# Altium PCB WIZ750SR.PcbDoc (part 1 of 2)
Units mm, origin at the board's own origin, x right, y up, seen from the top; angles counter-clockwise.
Board outline 45 x 30 mm, 4 copper layers (Top Layer, Internal Plane 1, Internal Plane 2, Bottom Layer); 93 components, 69 nets, 325 pads, 127 vias.
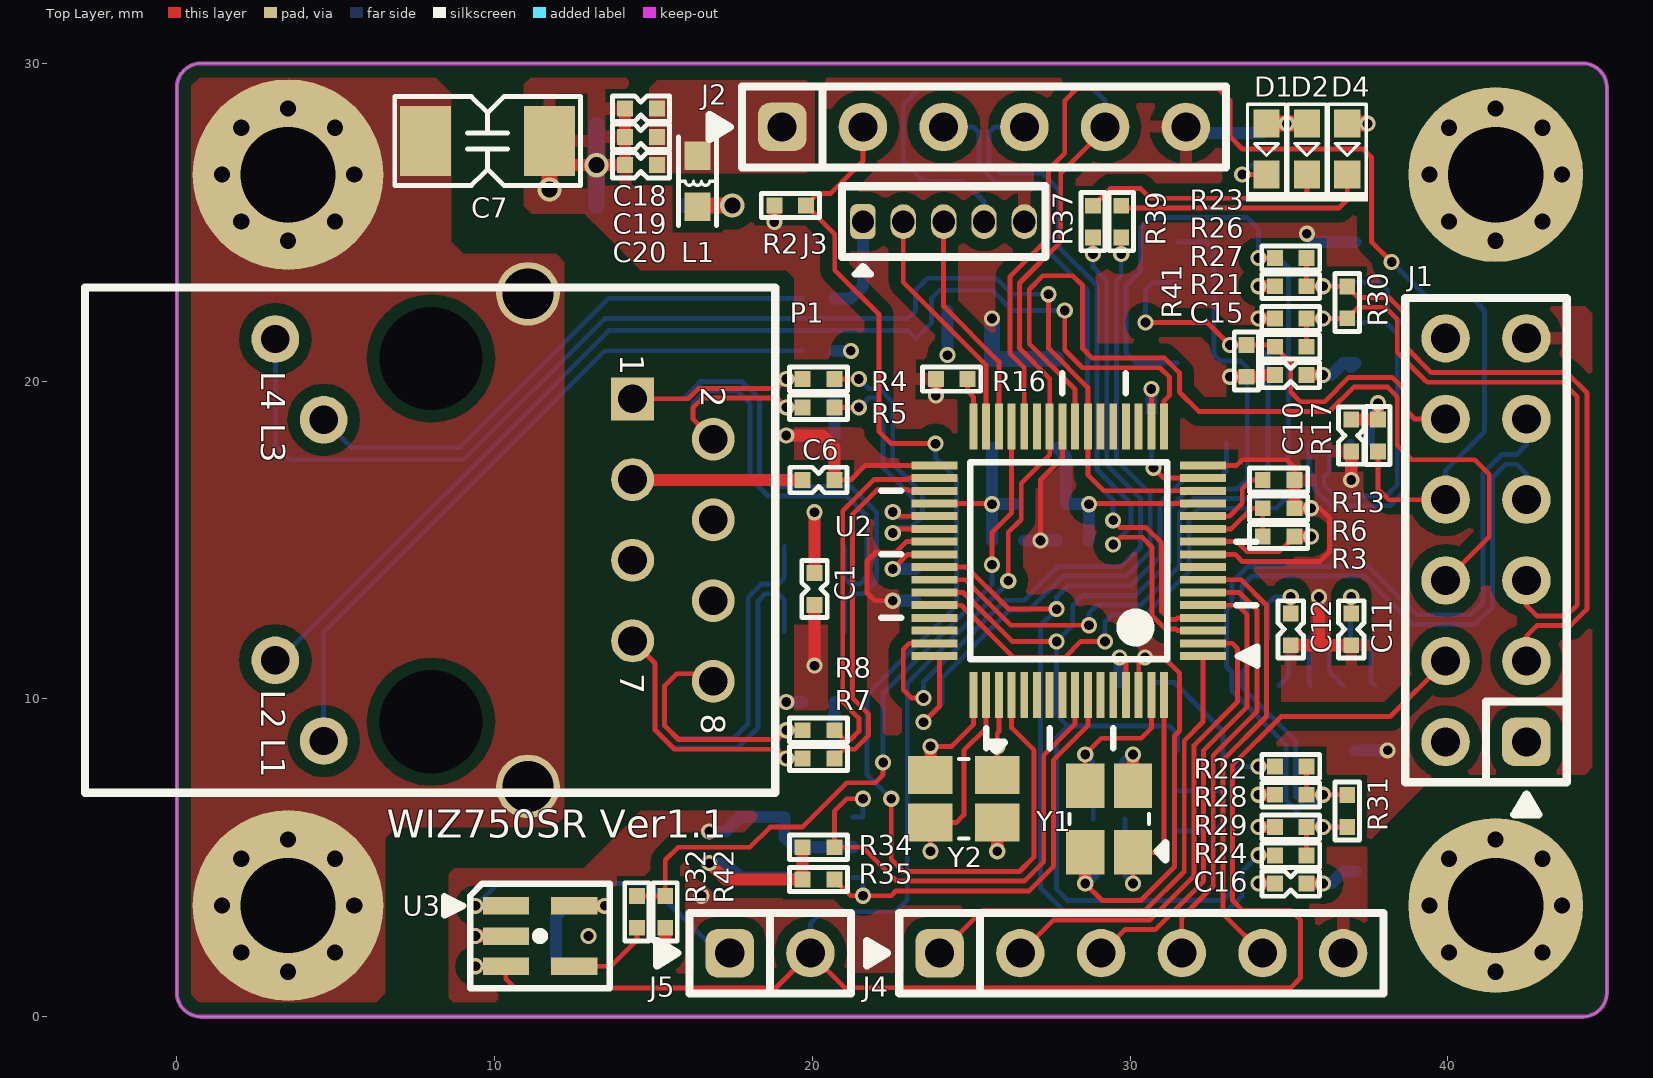
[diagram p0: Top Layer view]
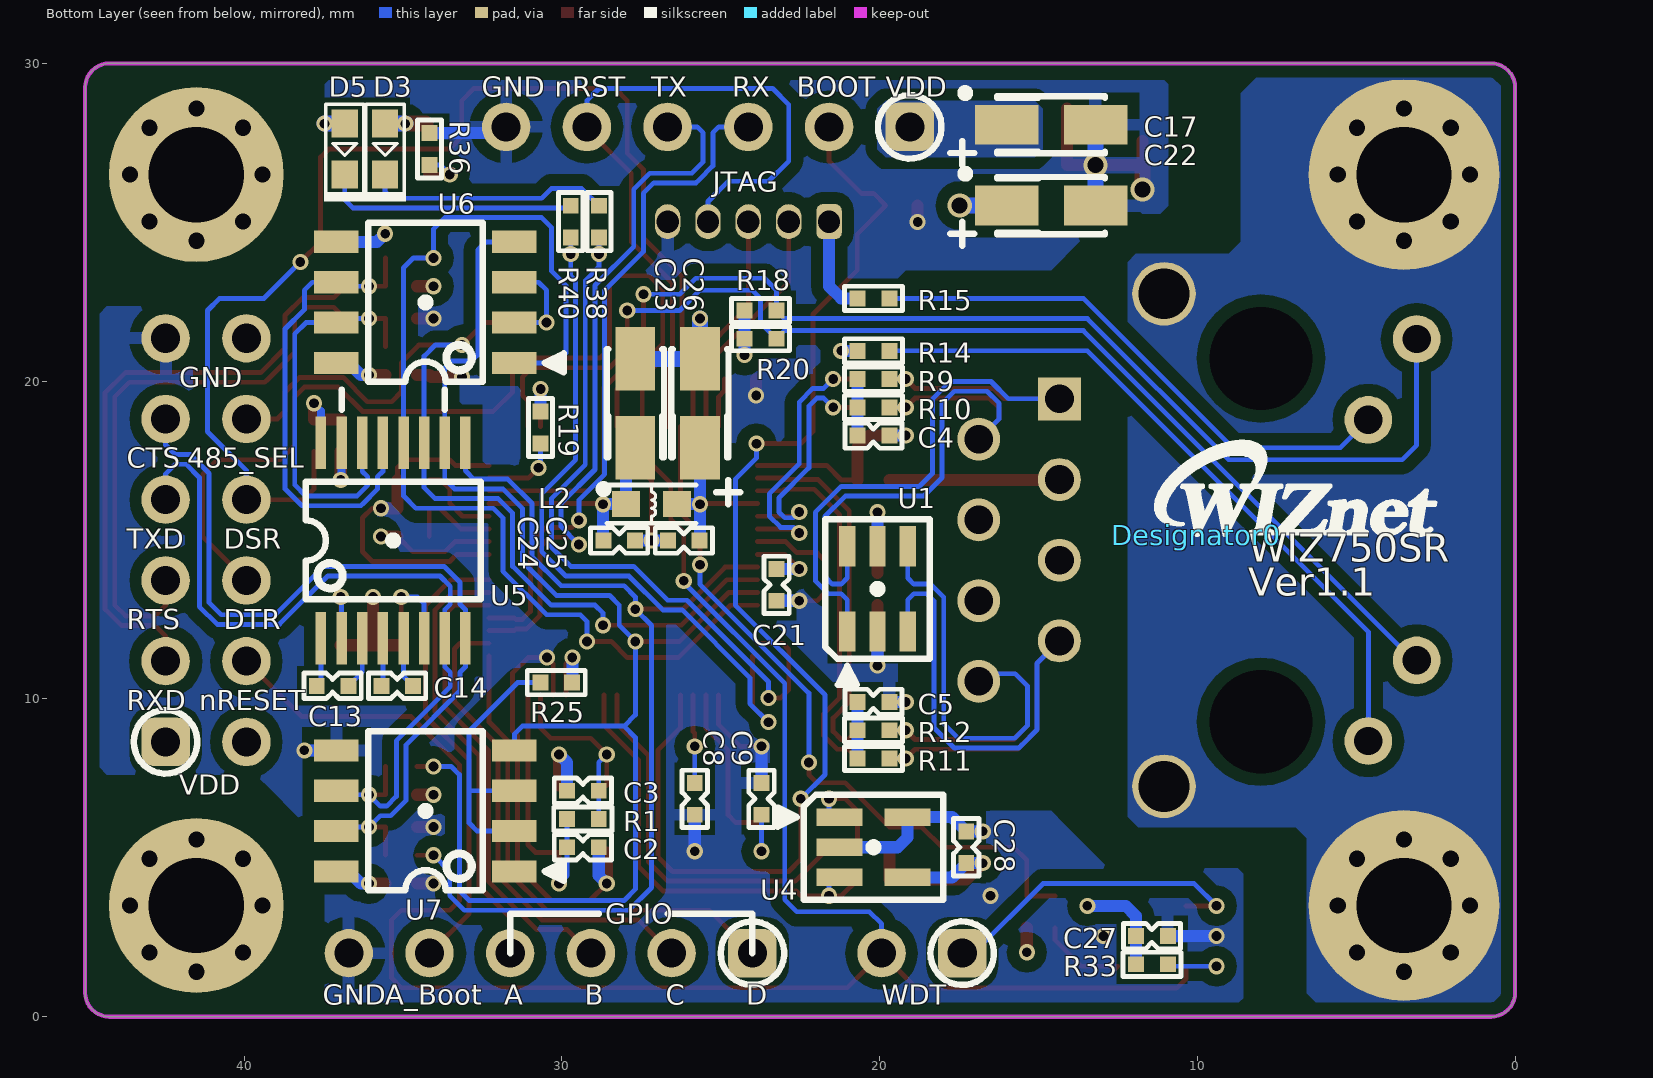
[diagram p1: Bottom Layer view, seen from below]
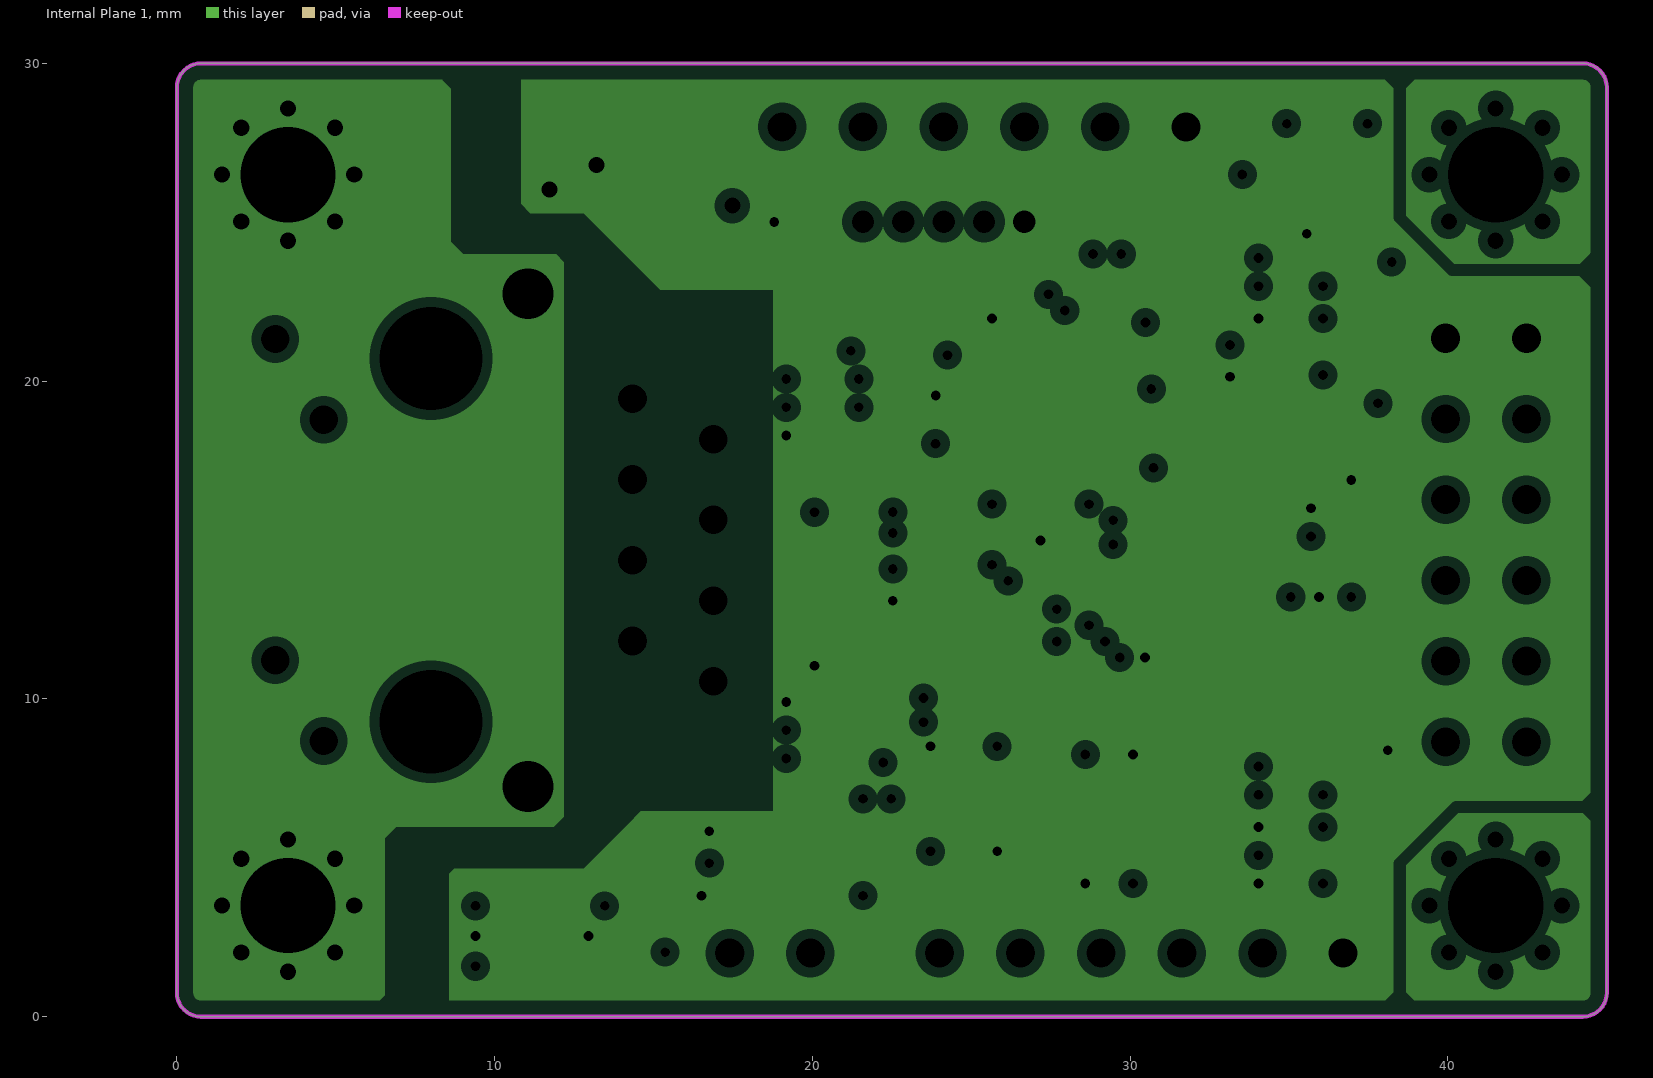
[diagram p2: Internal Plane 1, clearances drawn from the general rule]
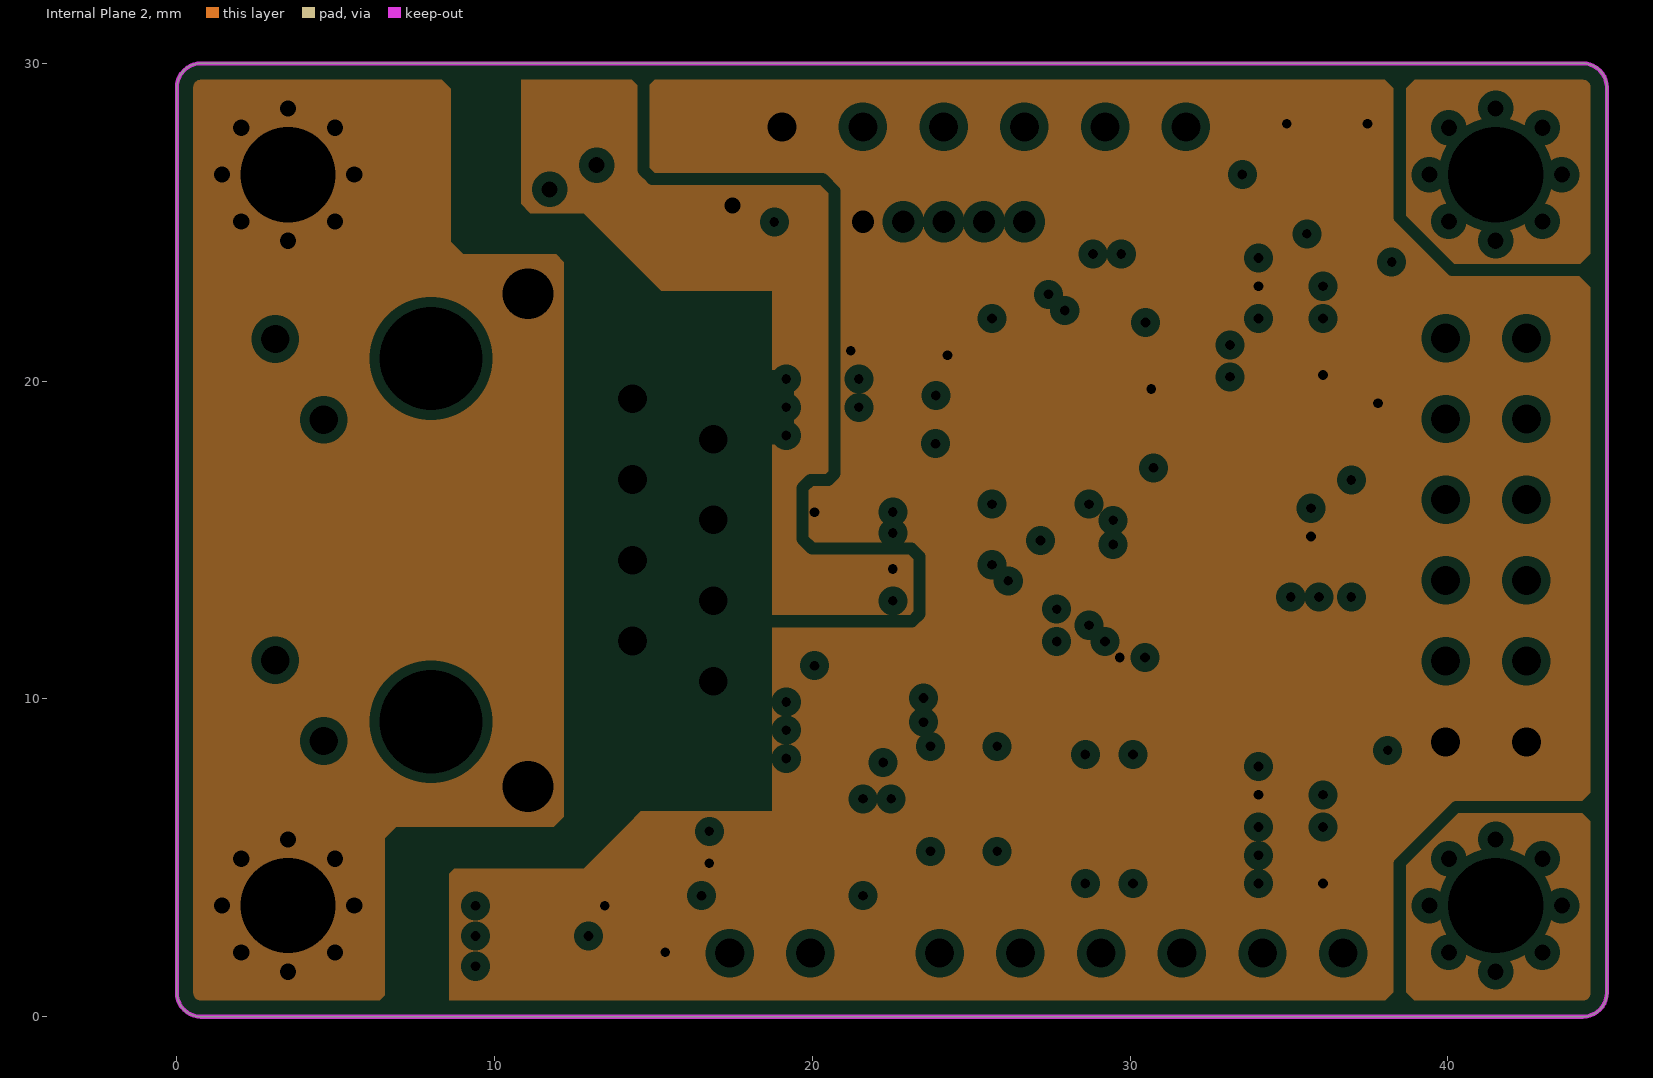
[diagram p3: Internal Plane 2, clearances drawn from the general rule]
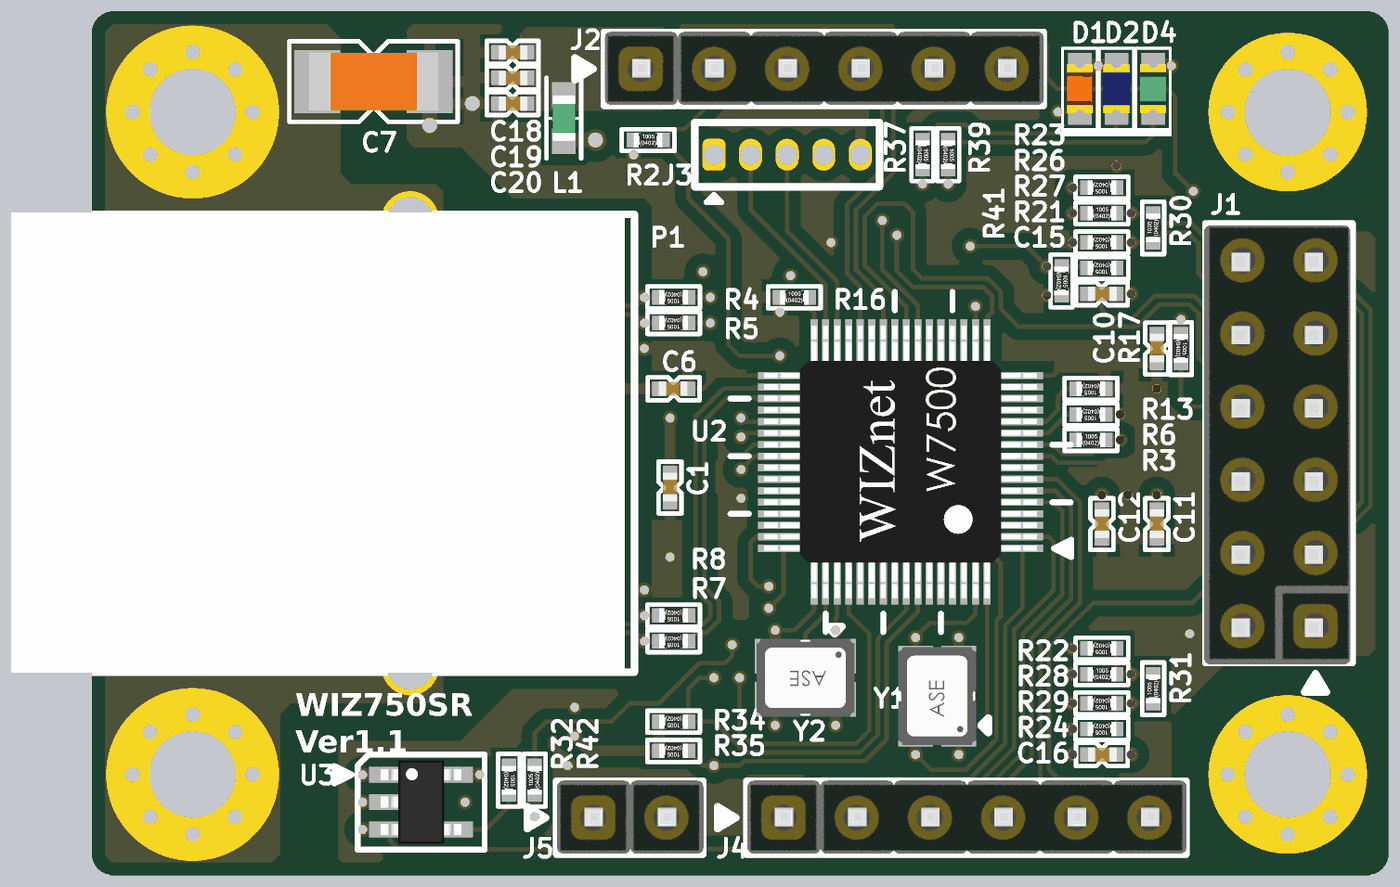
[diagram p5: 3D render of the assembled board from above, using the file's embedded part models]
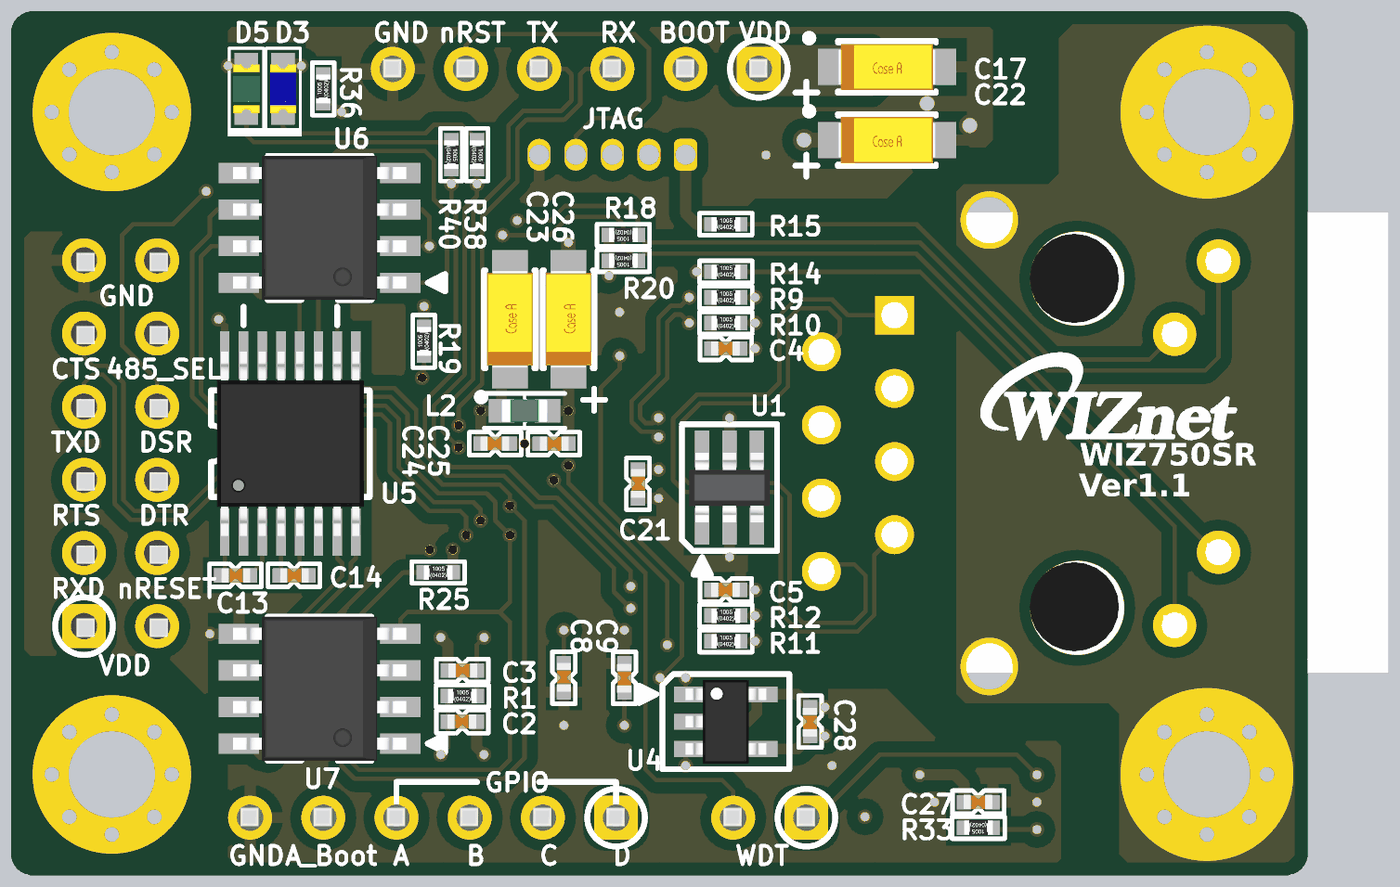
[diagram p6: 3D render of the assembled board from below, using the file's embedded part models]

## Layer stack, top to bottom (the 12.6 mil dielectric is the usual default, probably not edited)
Top Solder: solder mask 0.0102, Solder Resist, Dk 3.5
Top Layer: signal copper 0.0356
Dielectric1: core 0.32, FR-4, Dk 4.8
Internal Plane 1: plane copper 0.0356, net (Multiple Nets)
Dielectric5: prepreg 0.32, FR-4, Dk 4.8
Internal Plane 2: plane copper 0.0356, net (Multiple Nets)
Dielectric6: core 0.32, FR-4, Dk 4.8
Bottom Layer: signal copper 0.0356
Bottom Solder: solder mask 0.0102, Solder Resist, Dk 3.5

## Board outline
0,0.762 0,29.238 cw(c0.762,29.238) 0.762,30 44.238,30 cw(c44.238,29.238) 45,29.238 45,0.762 cw(c44.238,0.762) 44.238,0 0.762,0 cw(c0.762,0.762)

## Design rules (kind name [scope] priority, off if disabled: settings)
Clearance [All] p1: gap=0.15 except(0.381: Arc-Poly Track-Poly SMDPad-Poly THPad-Poly Via-Poly Fill-Poly Poly-Poly Poly-Region)
DiffPairsRouting [All] p1: maxlimit=0.254 minlimit=0.127 mostfreqgap=0.152 toplayer_minwidth=0.152 toplayer_maxwidth=0.381 toplayer_prefwidth=0.152 bottomlayer_minwidth=0.152 bottomlayer_maxwidth=0.381 bottomlayer_prefwidth=0.152 maxuncoupledlength=15.24
HoleSize [All] p1: absolutevalues=TRUE maxlimit=4.064 minlimit=0.025 maxpercent=80.000 minpercent=20.000
PlaneClearance [All] p1: clearance=0.305
PlaneConnect [All] p1: planeconnectstyle=Direct reliefexpansion=0.508 reliefentries=4 reliefconductorwidth=0.254 reliefairgap=0.254
PolygonConnect PolygonConnect_2 [IsPad vs IsNamedPolygon('Top Layer-GND') Or  IsNamedPolygon('Bottom Layer-GND')] p1: connectstyle=Relief reliefconductorwidth=0.381 reliefentries=4 polygonreliefangle="90 Angle" airgapwidth=0.381
PolygonConnect PolygonConnect_1 [IsVia] p2: connectstyle=Direct reliefconductorwidth=0.254 reliefentries=4 polygonreliefangle="90 Angle" airgapwidth=0.254
PolygonConnect [All] p3: connectstyle=Direct reliefconductorwidth=0.254 reliefentries=4 polygonreliefangle="90 Angle" airgapwidth=0.254
RoutingVias [All] p1: holewidth=0.305 width=0.508 viastyle="Through Hole" minholewidth=0.305 minwidth=0.508 maxholewidth=0.508 maxwidth=0.762
SolderMaskExpansion [All] p1: expansion=0
Width [All] p1: maxlimit=2.54 minlimit=0.102 preferedwidth=0.152 minimp=50.000000 maximp=50.000000 favimp=50.000000
26 further rules are at their usual default settings.

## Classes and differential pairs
component class 1.WIZ750SR_W7500P: C1 C2 C3 C4 C5 C6 C7 C8 C9 P1 R1 R2 R3 R4 R5 R6 R7 R8 R9 R10 R11 R12 R13 R14 R15 R16 R17 R18 R19 R20 U1 U2 Y1 Y2
component class 2.WIZ750SR_Transceiver: C10 C11 C12 C13 C14 C15 C16 J1 LD1 LD2 R21 R22 R23 R24 R25 R26 R27 R28 R29 R30 R31 R41 U5 U6 U7
differential pair MDI_T: +MDI_T_P -MDI_T_N
differential pair MDI_R: +MDI_R_P -MDI_R_N
differential pair MDI0_T: +MDI0_T_P -MDI0_T_N
differential pair MDI0_R: +MDI0_R_P -MDI0_R_N

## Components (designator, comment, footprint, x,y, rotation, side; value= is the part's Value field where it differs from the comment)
C1 "0.1uF" CAP-0402 20.066,13.462 r90 top
C2 "30pF" CAP-0402 29.337,5.334 r0 bottom
C3 "30pF" CAP-0402 29.337,7.112 r180 bottom
C4 "0.1uF" CAP-0402 20.193,18.288 r0 bottom
C5 "0.1uF" CAP-0402 20.193,9.906 r0 bottom
C6 "0.1uF" CAP-0402 20.193,16.891 r180 top
C7 "1nF/2kV" CAP-1808 9.779,27.559 r180 top
C8 "27pF" CAP-0402 25.815,6.858 r90 bottom
C9 "27pF" CAP-0402 23.715,6.858 r270 bottom
C10 "0.1uF" CAP-0402 36.957,18.288 r90 top
C11 "0.1uF" CAP-0402 36.957,12.192 r90 top
C12 "0.1uF" CAP-0402 35.052,12.192 r90 top
C13 "0.1uF" CAP-0402 37.211,10.414 r180 bottom
C14 "0.1uF" CAP-0402 35.179,10.414 r180 bottom
C15 "0.1uF" CAP-0402 35.052,20.193 r0 top
C16 "0.1uF" CAP-0402 35.052,4.191 r0 top
C17 "10uF/16V" "CAP-A Size" 14.605,28.067 r180 bottom
C18 "0.1uF" CAP-0402 14.605,28.575 r0 top
C19 "0.1uF" CAP-0402 14.605,27.686 r0 top
C20 "0.1uF" CAP-0402 14.605,26.797 r0 top
C21 "0.1uF" CAP-0402 23.241,13.589 r90 bottom
C22 "10uF/16V" "CAP-A Size" 14.605,25.527 r180 bottom
C23 "10uF/16V" "CAP-A Size" 27.686,19.304 r90 bottom
C24 "0.1uF" CAP-0402 28.194,14.986 r0 bottom
C25 "0.1uF" CAP-0402 26.162,14.986 r180 bottom
C26 "10uF/16V" "CAP-A Size" 25.654,19.304 r90 bottom
C27 "0.1uF" CAP-0402 11.43,2.54 r0 bottom
C28 "0.1uF" CAP-0402 17.272,5.334 r270 bottom
D1 "RED-0603" LED-0603-RED 34.29,27.305 r270 top
D2 "BLUE-0603" LED-0603-BLUE 35.56,27.305 r270 top
D3 "BLUE-0603" LED-0603-BLUE 35.56,27.305 r270 bottom
D4 "GREEN-0603" LED-0603-GREEN 36.83,27.305 r270 top
D5 "GREEN-0603" LED-0603-GREEN 36.83,27.305 r270 bottom
Designator0 "Comment" LOGO-WIZNET(SMALL) 10.033,15.164 r180 bottom
J1 "2.54mm 6x2 Pin Header DIP" IDC-2X6 42.466,8.65 r90 top locked
J2 "2.54mm 1x6 Pin Header DIP" IDC-1X6 19.05,28 r0 top locked
J3 "1.27mm_1x5_Pin_header_DIP" IDC-1X5(1.27MM) 21.59,25.019 r0 top
J4 "2.54mm 1x6 Pin Header DIP" IDC-1X6 24.003,2 r0 top
J5 "2.54mm Pin Header" IDC-1X2 17.399,2 r0 top locked
L1 "HH-1M1608-121JT" IND-0603 16.383,26.289 r270 top
L2 "HH-1M1608-121JT" IND-0603 27.178,16.129 r180 bottom
P1 "BS-RB10005" RJ45-125BAG1A 8,15 r270 top locked
R1 "1M" RES-0402#1 29.337,6.223 r180 bottom
R2 "4.7K" RES-0402#1 19.304,25.527 r0 top
R3 "4.7K" RES-0402#1 34.671,15.113 r0 top
R4 "2.2R" RES-0402#1 20.193,20.066 r180 top
R5 "2.2R" RES-0402#1 20.193,19.177 r180 top
R6 "4.7K" RES-0402#1 34.671,16.002 r180 top
R7 "2.2R" RES-0402#1 20.193,8.128 r180 top
R8 "2.2R" RES-0402#1 20.193,9.017 r180 top
R9 "49.9R/1%" RES-0402#1 20.193,20.066 r180 bottom
R10 "49.9R/1%" RES-0402#1 20.193,19.177 r180 bottom
R11 "49.9R/1%" RES-0402#1 20.193,8.128 r180 bottom
R12 "49.9R/1%" RES-0402#1 20.193,9.017 r180 bottom
R13 "4.7K" RES-0402#1 34.671,16.891 r180 top
R14 "330R" RES-0402#1 20.193,20.955 r180 bottom
R15 "330R" RES-0402#1 20.193,22.606 r180 bottom
R16 "6.19K/1%" RES-0402#1 24.384,20.066 r0 top
R17 "4.7K" RES-0402#1 37.795,18.288 r270 top
R18 "5.1K" RES-0402#1 23.749,22.225 r0 bottom
R19 "5.1K" RES-0402#1 30.67,18.542 r90 bottom
R20 "5.1K" RES-0402#1 23.749,21.336 r0 bottom
R21 "0R" RES-0402#1 35.052,21.082 r180 top
R22 "0R" RES-0402#1 35.052,7.874 r180 top
R23 "0R" RES-0402#1 35.052,23.876 r180 top
R24 "0R" RES-0402#1 35.052,5.08 r180 top
R25 "4.7K" RES-0402#1 30.175,10.516 r180 bottom
R26 "200R" RES-0402#1 35.052,22.987 r0 top
R27 "200R" RES-0402#1 35.052,21.971 r180 top
R28 "200R" RES-0402#1 35.052,6.985 r0 top
R29 "200R" RES-0402#1 35.052,5.969 r180 top
R30 "120R" RES-0402#1 36.83,22.479 r90 top
R31 "120R" RES-0402#1 36.83,6.477 r90 top
R32 "0R" RES-0402#1 14.478,3.302 r270 top
R33 "4.7K" RES-0402#1 11.43,1.651 r0 bottom
R34 "4.7K" RES-0402#1 20.193,5.334 r180 top
R35 "4.7K" RES-0402#1 20.193,4.318 r180 top
R36 "330R" RES-0402#1 34.163,27.305 r90 bottom
R37 "1K" RES-0402#1 28.829,25.019 r270 top
R38 "1K" RES-0402#1 28.829,25.019 r270 bottom
R39 "330R" RES-0402#1 29.718,25.019 r270 top
R40 "330R" RES-0402#1 29.718,25.019 r270 bottom
R41 "NC" RES-0402#1 33.655,20.637 r270 top
R42 "4.7K" RES-0402#2 15.367,3.302 r90 top
U1 "tpd4s009" SOT-23-6L 20.066,13.462 r90 bottom
U2 "W7500P" W7500-LQFP64 28.067,14.351 r180 top locked
U3 "STM6823RWY6F" SOT-23-5L 11.43,2.54 r0 top
U4 "24AA16T-I/OT" SOT-23-5L 20.193,5.334 r180 bottom
U5 "SP3232EBEY" TSSOP16(0.65/6.4) 35.306,14.986 r90 bottom locked
U6 "SP3485EN" SO-08 34.29,22.479 r0 bottom
U7 "SP3485EN" SO-08 34.29,6.477 r0 bottom
Y1 "12MHz" OSC-TZ1067B 29.337,6.223 r90 top
Y2 "25MHz" OSC-82J0626 24.765,6.858 r180 top

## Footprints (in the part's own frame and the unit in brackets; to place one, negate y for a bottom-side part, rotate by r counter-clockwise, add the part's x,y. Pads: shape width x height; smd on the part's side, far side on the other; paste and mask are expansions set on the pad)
CAP-0402 [mm]
  rect 0.5x0.5 smd: 1(-0.5,0) 2(0.5,0)
  silkscreen extent -0.9,-0.4 0.9,0.4, body extent -0.48,-0.25 0.52,0.25, height 0.6
CAP-1808 [mm] "Ceramic CAP 1808(4520)"
  rect 1.6x2.2 smd: 1(-1.95,0) 2(1.95,0)
  silkscreen extent -2.92,-1.4 2.92,1.4, body extent -2.25,-1.02 2.25,1.01, height 2
"CAP-A Size" [mm] "Tantal CAP A Size EIA/IECQ 3216"
  rect 2x1.25 smd: 1(-1.4,0) 2(1.4,0)
  silkscreen extent -3.17,-1.27 1.7,1.12, body extent -1.7,-0.8 1.7,0.8, height 1.75
IDC-1X2 [mil]
  rrect50% 60x60 hole 36: 1(0,0)
  round 60 hole 36: 2(100,0)
  silkscreen extent -90,-50 150,50, body extent -49,-49 151,51, height 336
IDC-1X5(1.27MM) [mm]
  rrect50% 0.8x1.1 hole 0.7: 1(0,0)
  oval 0.8x1.1 hole 0.7: 2(1.27,0) 3(2.54,0) 4(3.81,0) 5(5.08,0)
  silkscreen extent -0.66,-1.65 5.74,1.11
IDC-1X6 [mil] "6-Way 2.54 mm Male Header"
  rrect50% 60x60 hole 36: 1(0,0)
  round 60 hole 36: 2(100,0) 3(200,0) 4(300,0) 5(400,0) 6(500,0)
  silkscreen extent -90,-50 550,50, body extent -49,-49 551,51, height 336
IDC-2X6 [mil]
  rrect50% 60x60 hole 36: 1(0,0)
  round 60 hole 36: 2(0,100) 3(100,0) 4(100,100) 5(200,0) 6(200,100) 7(300,0) 8(300,100) 9(400,0) 10(400,100) 11(500,0) 12(500,100)
  silkscreen extent -90,-50 550,150, body extent -52,-48 548,152, height 336
IND-0603 [mm] "Inductor 0603(1608)"
  rect 0.89x0.82 smd: 1(-0.8,0) 2(0.8,0)
  silkscreen extent -1.4,-0.6 1.4,0.6, body extent -0.8,-0.4 0.8,0.4, height 0.95
LED-0603-BLUE [mm] "LED-0603-BLUE"
  rect 0.89x0.82 smd: 1(-0.8,0) 2(0.8,0)
  silkscreen extent -1.41,-0.65 1.65,0.65, body extent -0.85,-0.45 0.85,0.45, height 0.9
LED-0603-GREEN [mm] "LED-0603-GREEN"
  rect 0.89x0.82 smd: 1(-0.8,0) 2(0.8,0)
  silkscreen extent -1.41,-0.65 1.65,0.65, body extent -0.85,-0.45 0.85,0.45, height 0.9
LED-0603-RED [mm] "LED-0603-RED"
  rect 0.89x0.82 smd: 1(-0.8,0) 2(0.8,0)
  silkscreen extent -1.41,-0.65 1.65,0.65, body extent -0.85,-0.45 0.85,0.45, height 0.9
LOGO-WIZNET(SMALL) [mm]
  silkscreen extent -1.27,0 7.52,2.93
OSC-82J0626 [mm]
  rect 1.4x1.2 smd: 1(-1.05,-0.75) 2(1.05,-0.75) 3(1.05,0.75) 4(-1.05,0.75)
  silkscreen extent -1.27,-1.78 0.15,1.25, body extent -1.7,-1.35 1.7,1.35, height 1.06
OSC-TZ1067B [mm]
  rect 1.4x1.2 smd: 1(-1.05,-0.75) 2(1.05,-0.75) 3(1.05,0.75) 4(-1.05,0.75)
  silkscreen extent -1.27,-1.78 0.15,1.25, body extent -1.7,-1.35 1.7,1.35, height 1.06
RES-0402#1 [mm]
  rect 0.5x0.5 smd: 1(-0.5,0) 2(0.5,0)
  silkscreen extent -0.91,-0.38 0.91,0.38, body extent -0.5,-0.25 0.5,0.25, height 0.35
RES-0402#2 [mm]
  rect 0.5x0.5 smd: 1(-0.5,-0.004) 2(0.5,-0.004)
  silkscreen extent -0.91,-0.38 0.91,0.38, body extent -0.5,-0.25 0.5,0.25, height 0.35
RJ45-125BAG1A [mm]
  round 1.5 hole 0.89: L1(6.325,-3.38) L2(3.785,-4.9) L3(-3.785,-3.38) L4(-6.325,-4.9)
  rect 1.35x1.35 hole 0.9: R1(-4.445,6.34)
  round 1.35 hole 0.9: R2(-3.175,8.88) R3(-1.905,6.34) R4(-0.635,8.88) R5(0.635,6.34) R6(1.905,8.88) R7(3.175,6.34) R8(4.445,8.88)
  round 2 hole 1.6: R9(-7.75,3.05) R10(7.75,3.05)
  round 1.8 hole 3.25: ""(-5.715,0) ""(5.715,0)
  silkscreen extent -7.95,-10.89 7.95,10.83, body extent -8.03,-10.8 7.97,10.5, height 13.1
SO-08 [mm]
  rect 1.4x0.7 smd: 1(-2.8,1.905) 2(-2.8,0.635) 3(-2.8,-0.635) 4(-2.8,-1.905) 5(2.8,-1.905) 6(2.8,-0.635) 7(2.8,0.635) 8(2.8,1.905)
  silkscreen extent -4.35,-2.5 1.8,2.5, body extent -3.01,-2.5 3.01,2.5, height 1.75
SOT-23-5L [mm]
  rect 1.45x0.55 smd: 1(-1.075,0.95) 2(-1.075,0) 3(-1.075,-0.95) 4(1.075,-0.95) 5(1.075,0.95)
  silkscreen extent -3.01,-1.65 2.2,1.65, body extent -1.4,-1.45 1.4,1.45, height 1.45
SOT-23-6L [mm]
  rect 1.27x0.508 smd: 1(-1.34,0.95) 2(-1.34,0) 3(-1.34,-0.95) 4(1.34,-0.95) 5(1.34,0) 6(1.34,0.95)
  silkscreen extent -3.02,-1.65 2.2,1.65, body extent -1.21,-1.4 1.21,1.4, height 1.09
TSSOP16(0.65/6.4) [mil]
  rect 65x13 smd: 1(-121.04,89.57) 2(-121.04,63.98) 3(-121.04,38.39) 4(-121.04,12.8) 5(-121.04,-12.8) 6(-121.04,-38.39) 7(-121.04,-63.98) 8(-121.04,-89.57) 9(121.04,-89.57) 10(121.04,-63.98) 11(121.04,-38.39) 12(121.04,-12.8) 13(121.04,12.8) 14(121.04,38.39) 15(121.04,63.98) 16(121.04,89.57)
  silkscreen extent -73,-108 187,108, body extent -126,-100 126,100, height 47
W7500-LQFP64 [mm] "WIZnet ARM Cortex-M0, LQFP64, Pitch 0.40mm"
  rect 1.45x0.25 smd: 1(-4.225,3) 2(-4.225,2.6) 3(-4.225,2.2) 4(-4.225,1.8) 5(-4.225,1.4) 6(-4.225,1) 7(-4.225,0.6) 8(-4.225,0.2) 9(-4.225,-0.2) 10(-4.225,-0.6) 11(-4.225,-1) 12(-4.225,-1.4) 13(-4.225,-1.8) 14(-4.225,-2.2) 15(-4.225,-2.6) 16(-4.225,-3) 33(4.225,-3) 34(4.225,-2.6) 35(4.225,-2.2) 36(4.225,-1.8) 37(4.225,-1.4) 38(4.225,-1) 39(4.225,-0.6) 40(4.225,-0.2) 41(4.225,0.2) 42(4.225,0.6) 43(4.225,1) 44(4.225,1.4) 45(4.225,1.8) 46(4.225,2.2) 47(4.225,2.6) 48(4.225,3)
  rect 0.25x1.45 smd: 17(-3,-4.225) 18(-2.6,-4.225) 19(-2.2,-4.225) 20(-1.8,-4.225) 21(-1.4,-4.225) 22(-1,-4.225) 23(-0.6,-4.225) 24(-0.2,-4.225) 25(0.2,-4.225) 26(0.6,-4.225) 27(1,-4.225) 28(1.4,-4.225) 29(1.8,-4.225) 30(2.2,-4.225) 31(2.6,-4.225) 32(3,-4.225) 49(3,4.225) 50(2.6,4.225) 51(2.2,4.225) 52(1.8,4.225) 53(1.4,4.225) 54(1,4.225) 55(0.6,4.225) 56(0.2,4.225) 57(-0.2,4.225) 58(-0.6,4.225) 59(-1,4.225) 60(-1.4,4.225) 61(-1.8,4.225) 62(-2.2,4.225) 63(-2.6,4.225) 64(-3,4.225)
  silkscreen extent -5.92,-5.9 5.9,5.9, body extent -4.73,-4.74 4.73,4.72, height 1

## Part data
C1 C2 C3 C4 C5 C6 C8 C9 C10 C11 C12 C13 C14 C15 C16 C18 C19 C20 C21 C24 C25 C27 C28: library part CAP-0402, "Ceramic CAP 0402(1005)"
C7: library part CAP-1808, "Ceramic CAP 1808(4520)"
C17 C22 C23 C26: library part "CAP-A Size", "Tantla CAP A Size EIA/IECQ 3216"
D1 D2 D3 D4 D5: library part LED-0603, "LED-0603"
J1: library part "Header 6X2", "Header, 6-Pin, Dual row"
J2 J4: library part "Header 6", "Header, 6-Pin"
J5: library part "Header 2", "Header, 2-Pin"
L1 L2: library part IND-0603, "Inductor 0603(1608)"
P1: library part RB1-125BAG1A, "10/100 BASE-TX MAGJACK"
R1 R2 R3 R4 R5 R6 R7 R8 R9 R10 R11 R12 R13 R14 R15 R16 R17 R18 R19 R20 R21 R22 R23 R24 R25 R26 R27 R28 R29 R30 R31 R32 R33 R34 R35 R36 R37 R38 R39 R40 R41 R42: library part RES-0402, "RES-0402"
U1: "6-PIN SOT DBVor DCK Package"
U2: "WIZnet ARM Cortex-M0, Add PHY"
U3: library part STM6823, "Manual_Reset SOT23-5"
U4: library part 24AAxxT-i-OT, "SOT-23"
U5: "True +3.0V to +5.5V RS-232 Transceivers TSSOP16"
U6 U7: "RS485 Transceiver"
Y1: library part OSC-TZ1067B-12MHz, "X-tal 12MHz,3.2x2.5 SMD, CL=20pF"
Y2: library part OSC-82J0626-25MHz, "X-tal 25MHz,3.2x2.5 SMD, CL=18pF"

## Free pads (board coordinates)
  round 6 hole 3: ""(3.5,3.5) ""(3.5,26.5)
  round 5.5 hole 3: ""(41.5,3.5) ""(41.5,26.5)

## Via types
v1: diameter 0.508, hole 0.305, Top Layer to Bottom Layer, tented both sides, 92 vias
v2: diameter 0.762, hole 0.508, Top Layer to Bottom Layer, tented both sides, 35 vias

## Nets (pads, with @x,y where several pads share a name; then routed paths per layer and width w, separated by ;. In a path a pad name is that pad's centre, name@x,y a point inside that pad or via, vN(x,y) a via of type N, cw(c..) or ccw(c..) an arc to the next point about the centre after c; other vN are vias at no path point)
100M_LED: P1.L2 R20.1 U2.17 | length 37.1
  Top Layer w0.152: v1(27.94,22.225) 27.94,20.98 28.499,20.422 30.937,20.422 31.242,20.117 31.242,19.558 31.067,19.383 U2.17@31.067,18.576
  Bottom Layer w0.152: P1.L2@3.1,11.215 3.214,11.215 13.589,21.59 22.995,21.59 R20.1@23.249,21.336 23.749,21.836 23.749,22.606 24.003,22.86 25.654,22.86 26.289,22.225 v1(27.94,22.225)
422_TXD+: J1.7 R22.1 R28.2 R31.2 U5.7 U7.6 | length 26.8
  Top Layer w0.152: R22.1@35.552,7.874 R28.2@35.552,6.985 v1(36.068,6.985) R31.2@36.822,6.985
  Bottom Layer w0.152: U7.6@36.963,6.985 v1(36.068,6.985) 35.712,6.629 35.509,6.629 35.204,6.934 35.204,8.687 33.508,10.383 33.508,10.837 33.681,11.01 U5.7@33.681,11.912 33.681,12.813 33.508,12.986 33.508,13.544 33.833,13.868 37.364,13.868 38.888,12.344 40.843,12.344 41.402,12.903 41.402,16.968 41.822,17.388 42.164,17.388 42.466,17.086 J1.7@42.466,16.27
422_TXD-: J1.9 R24.1 R29.1 R31.1 U5.8 U7.7 | length 27.8
  Top Layer w0.152: R24.1@35.552,5.08 R29.1@35.552,5.969 v1(36.068,5.969) R31.1@36.822,5.969
  Bottom Layer w0.152: U7.7@36.963,5.969 v1(36.068,5.969) 35.712,6.325 35.383,6.325 34.9,6.808 34.9,8.561 33.204,10.257 33.204,10.837 33.031,11.01 U5.8@33.031,11.912 33.031,12.813 33.204,12.986 33.204,13.67 33.707,14.173 37.49,14.173 39.014,12.649 40.717,12.649 41.097,13.029 41.097,17.094 41.695,17.692 42.164,17.692 42.466,17.994 J1.9@42.466,18.81
485+: J1.3 R23.1 R26.2 R30.2 U5.13 U6.6 | length 34.9
  Top Layer w0.152: R23.1@35.552,23.876 R26.2@35.552,22.987 v1(36.068,22.987) R30.2@36.822,22.987 ; R30.2@36.83,22.979 37.178,22.631 38.15,22.631 38.71,22.072 38.71,21.031 39.472,20.269 43.738,20.269 44.374,19.633 44.374,12.828 44.285,12.738 43.854,12.308 42.799,12.308 42.466,11.975 J1.3@42.466,11.19
  Bottom Layer w0.152: U5.13@35.631,18.06 35.631,17.159 35.804,16.986 35.804,16.597 36.233,16.167 36.323,16.078 38.176,16.078 38.71,16.612 38.71,21.641 38.1,22.25 38.1,22.86 37.846,23.114 U6.6@37.09,23.114 ; v1(36.068,22.987) U6.6@36.963,22.987
485-: J1.5 R21.1 R27.1 R30.1 U5.14 U6.7 | length 31.7
  Top Layer w0.152: R21.1@35.552,21.082 R27.1@35.552,21.971 v1(36.068,21.971) 36.822,21.971 R30.1@36.83,21.979 37.178,22.327 38.024,22.327 38.405,21.946 38.405,20.905 39.256,20.054 39.345,19.964 43.612,19.964 44.069,19.507 44.069,12.954 43.727,12.612 42.799,12.612 42.466,12.945 J1.5@42.466,13.73
  Bottom Layer w0.152: v1(36.068,21.971) U6.7@36.963,21.971 ; U5.14@36.281,18.06 36.281,17.159 36.108,16.986 36.108,16.724 36.449,16.383 38.05,16.383 38.405,16.738 38.405,21.488 38.049,21.844 U6.7@37.09,21.844
485_SEL: J1.10 R21.2 R41.1 U2.42 U5.11 U6.2 U6.3 | length 34.9
  Top Layer w0.152: U2.42@23.842,13.751 24.806,13.751 26.238,12.319 v1(28.702,12.319) ; v1(30.48,21.844) 32.432,21.844 v1(33.139,21.137) R41.1@33.655,21.137 34.497,21.137 R21.2@34.552,21.082 35.052,20.582 35.052,19.66 35.357,19.355 36.119,19.355 36.881,20.117 38.252,20.117 38.71,19.66 38.71,19.05 38.95,18.81 J1.10@39.926,18.81
  Bottom Layer w0.152: v1(28.702,12.319) 28.702,12.7 28.956,12.954 30.328,12.954 31.547,14.173 31.547,15.85 32.004,16.307 33.985,16.307 34.331,16.653 U5.11@34.331,18.06 34.331,20.787 33.981,21.137 v1(33.139,21.137) ; U6.2@31.49,21.844 v1(30.48,21.844) 30.48,22.86 30.734,23.114 U6.3@31.49,23.114
APP_BOOT: J4.5 U2.7 | length 14.4
  Top Layer w0.152: U2.7@32.292,13.751 33.493,13.751 34.29,12.954 34.29,9.449 32.918,8.077 32.918,3.245 J4.5@34.163,2
BOOT: J2.2 R2.2 U2.52 | length 38.5
  Top Layer w0.152: J2.2@21.59,28 21.59,26.924 20.574,25.908 20.185,25.908 R2.2@19.804,25.527 20.701,24.63 20.701,23.495 22.098,22.098 22.098,18.415 22.479,18.034 v1(23.876,18.034) ; v1(22.479,6.858) 22.479,4.953 22.86,4.572 26.518,4.572 26.975,5.029 26.975,8.382 26.267,9.09 U2.52@26.267,10.126
  Bottom Layer w0.152: v1(22.479,6.858) 21.717,7.62 21.717,10.135 24.536,12.954 24.536,16.916 23.876,17.577 v1(23.876,18.034)
CH_GND: C7.2 P1.R9 P1.R10 pad.@3.5,3.5 pad.@3.5,26.5
  other v2: 3.5,1.417 2.027,2.027 4.973,2.027 1.417,3.5 5.583,3.5 2.027,4.973 4.973,4.973 3.5,5.583 3.5,24.417 2.027,25.027 4.973,25.027 1.417,26.5 5.583,26.5 2.027,27.973 4.973,27.973 3.5,28.583
DSR: J1.8 R17.2 U2.28 | length 39.6
  Top Layer w0.152: U2.28@26.667,18.576 26.667,20.425 26.213,20.879 26.213,23.292 27.432,24.511 27.432,26.67 27.94,27.178 27.94,28.829 28.321,29.21 32.766,29.21 33.147,28.829 33.147,27.686 33.528,27.305 37.338,27.305 37.592,27.051 37.592,24.384 v1(38.227,23.749) ; R17.2@37.795,17.788 37.795,16.612 38.137,16.27 J1.8@39.926,16.27
  Bottom Layer w0.152: v1(38.227,23.749) 39.37,22.606 40.767,22.606 41.148,22.225 41.148,18.415 39.926,17.193 J1.8@39.926,16.27
DTR: J1.6 U2.24 | length 29.1
  Top Layer w0.152: U2.24@28.267,18.576 28.267,19.739 26.822,21.184 26.822,22.885 27.254,23.317 28.194,23.317 28.499,23.012 28.499,21.031 28.804,20.726 31.09,20.726 31.547,20.269 31.547,19.66 32.156,19.05 36.271,19.05 37.033,19.812 38.1,19.812 38.405,19.507 38.405,17.983 38.862,17.526 40.843,17.526 41.3,17.069 41.3,15.104 J1.6@39.926,13.73
EXPANSION_GPIO_A: J4.4 U2.6 | length 13.7
  Top Layer w0.152: J4.4@31.623,2 31.623,3.124 32.614,4.115 32.614,8.23 33.985,9.601 33.985,12.802 33.436,13.351 U2.6@32.292,13.351
EXPANSION_GPIO_B: J4.3 U2.5 | length 14.6
  Top Layer w0.152: J4.3@29.083,2 29.826,2.743 30.785,2.743 32.309,4.267 32.309,8.382 33.68,9.754 33.68,12.649 33.379,12.951 U2.5@32.292,12.951
EXPANSION_GPIO_C: J4.2 U2.2 | length 15.3
  Top Layer w0.152: J4.2@26.543,2 27.591,3.048 30.632,3.048 32.004,4.42 32.004,8.534 33.376,9.906 33.376,11.582 33.207,11.751 U2.2@32.292,11.751
EXPANSION_GPIO_D: J4.1 U2.1 | length 15.8
  Top Layer w0.152: J4.1@24.003,2 25.356,3.353 30.48,3.353 31.699,4.572 31.699,8.687 32.292,9.28 U2.1@32.292,11.351
GND: C1.1 C2.1 C3.1 C4.1 C5.1 C6.1 C7.1 C8.1 C9.1 C10.1 C11.1 C12.1 C15.1 C16.1 C17.2 C18.1 C19.1 C20.1 C21.1 C22.2 C23.2 C24.1 C25.1 C26.2 C27.1 C28.1 J1.11 J1.12 J2.6 J3.5 J4.6 R2.1 R6.1 R13.1 R16.1 R27.2 R29.2 R36.2 R41.2 U1.2 U2.9 U2.16 U2.25 U2.33 U2.39 U2.49 U2.62 U3.2 U4.2 U4.5 U5.15 U6.5 U7.5 Y1.2 Y1.4 Y2.2 Y2.4 | length 88.1
  Top Layer w0.152: C6.1@20.693,16.891 21.209,16.891 21.669,17.351 U2.33@23.842,17.351 ; v1(22.53,13.089) 21.963,13.089 21.717,13.335 21.717,14.351 21.971,14.605 22.606,14.605 22.952,14.951 U2.39@23.842,14.951 ; v1(23.715,8.509) 24.384,8.509 25.067,9.192 U2.49@25.067,10.126 ; v1(27.178,14.986) 27.178,16.891 27.867,17.58 U2.25@27.867,18.576 ; v1(28.587,4.191) 29.12,3.658 30.328,3.658 31.394,4.724 31.394,8.839 31.547,8.992 31.547,10.82 31.064,11.303 v1(30.467,11.303) 30.267,11.103 U2.62@30.267,10.126 ; U2.9@32.292,14.551 33.303,14.551 33.528,14.326 35.966,14.326 36.271,14.63 36.271,15.697 35.966,16.002 v1(35.687,16.002) ; U2.16@32.292,17.351 33.353,17.351 33.528,17.526 34.925,17.526 35.171,17.28 R13.1@35.171,16.891
  Top Layer w0.381: v1(9.398,2.54) U3.2@10.355,2.54 ; C7.1@11.729,27.559 11.729,26.797 v2(13.208,26.797) C20.1@14.105,26.797 C19.1@14.105,27.686 C18.1@14.105,28.575 ; v1(18.804,25.011) R2.1@18.804,25.527 ; v1(19.177,18.288) 20.32,18.288 20.693,17.915 C6.1@20.693,16.891 ; v1(20.066,11.049) C1.1@20.066,12.962 ; Y2.2@23.715,7.608 v1(23.715,8.509) ; v1(23.884,19.55) R16.1@23.884,20.066 ; v1(25.815,5.207) Y2.4@25.815,6.108 ; v1(28.587,4.191) Y1.4@28.587,5.173 ; Y1.2@30.087,7.273 v1(30.087,8.255) ; v1(33.139,20.138) R41.2@33.655,20.138 34.108,20.138 34.163,20.193 C15.1@34.552,20.193 ; v1(34.036,4.191) C16.1@34.552,4.191 ; v1(34.036,5.969) R29.2@34.552,5.969 ; v1(34.036,21.971) R27.2@34.552,21.971 ; C12.1@35.052,11.692 35.941,11.692 ; R13.1@35.171,16.891 R6.1@35.171,16.002 v1(35.687,16.002) ; v1(35.941,13.208) 35.941,11.692 ; C11.1@36.957,11.692 35.941,11.692 ; v1(36.957,16.891) C10.1@36.957,17.788
  Top Layer w0.508: v2(11.729,26.035) C7.1@11.729,26.797
  Bottom Layer w0.254: U5.15@36.931,18.06 36.931,16.917 v1(36.957,16.891)
  Bottom Layer w0.381: v1(9.398,2.54) C27.1@10.93,2.54 ; v1(16.756,5.834) C28.1@17.272,5.834 17.722,6.284 U4.5@19.118,6.284 19.118,5.647 19.431,5.334 U4.2@21.268,5.334 ; v1(19.177,9.906) C5.1@19.693,9.906 ; v1(19.177,18.288) C4.1@19.693,18.288 ; v1(20.066,11.049) U1.2@20.066,12.122 ; v1(22.53,13.089) C21.1@23.241,13.089 ; C9.1@23.715,7.358 v1(23.715,8.509) ; v1(25.815,5.207) C8.1@25.815,6.358 ; C25.1@26.662,14.986 v1(27.178,14.986) C24.1@27.694,14.986 ; v1(28.587,4.191) 28.837,4.441 C2.1@28.837,5.334 ; C3.1@29.837,7.112 29.837,8.005 v1(30.087,8.255) ; J2.6@31.75,28 31.945,27.805 R36.2@34.163,27.805 ; v1(35.56,24.638) 35.814,24.384 U6.5@37.09,24.384 ; U7.5@37.09,8.382 v1(38.1,8.382)
  Bottom Layer w0.508: C22.2@13.208,25.53 v2(13.208,26.797) C17.2@13.208,28.064 ; C26.2@25.654,20.704 v1(25.654,21.971) ; C26.2@25.781,20.701 C23.2@27.686,20.701
  other v1: 12.954,2.54 16.51,3.81
LED_0: P1.L4 R18.1 U2.14 U2.23 | length 40.8
  Top Layer w0.152: v1(27.432,22.733) 27.432,21.031 28.667,19.796 U2.23@28.667,18.576 28.667,17.053 29.169,16.551 U2.14@32.292,16.551
  Bottom Layer w0.152: P1.L4@3.1,21.325 3.1,17.982 3.556,17.526 9.017,17.526 13.462,21.971 22.995,21.971 R18.1@23.249,22.225 23.249,22.868 23.622,23.241 25.781,23.241 26.289,22.733 v1(27.432,22.733)
LED_1: R19.1 U2.15 | length 2.5
  Top Layer w0.152: v1(30.734,17.272) 31.055,16.951 U2.15@32.292,16.951
  Bottom Layer w0.152: R19.1@30.67,18.042 30.67,17.335 v1(30.734,17.272)
MDI0_R_N: R8.1 U2.34 | length 11.5
  Top Layer w0.152: R8.1@20.693,9.017 20.985,8.725 21.209,8.725 21.463,8.979 21.463,9.398 20.955,9.906 20.955,15.925 21.933,16.903 22.993,16.903 23.041,16.951 U2.34@23.842,16.951
MDI0_R_P: R7.1 U2.35 | length 11.5
  Top Layer w0.152: R7.1@20.693,8.128 20.985,8.42 21.335,8.42 21.768,8.853 21.768,9.524 21.26,10.032 21.26,15.799 22.06,16.599 22.993,16.599 23.041,16.551 U2.35@23.842,16.551
MDI0_T_N: R5.1 U2.37 | length 7.6
  Top Layer w0.152: R5.1@20.693,19.177 v1(21.463,19.177) ; v1(22.53,15.881) 22.66,15.751 U2.37@23.842,15.751
  Bottom Layer w0.152: v1(21.463,19.177) 21.755,19.469 21.971,19.469 22.225,19.215 22.225,17.272 23.165,16.332 23.165,15.881 22.987,15.703 22.708,15.703 v1(22.53,15.881)
MDI0_T_P: R4.1 U2.38 | length 8.6
  Top Layer w0.152: R4.1@20.693,20.066 v1(21.463,20.066) ; v1(22.53,15.221) 22.66,15.351 U2.38@23.842,15.351
  Bottom Layer w0.152: v1(21.463,20.066) 21.755,19.774 22.097,19.774 22.53,19.341 22.53,17.398 23.47,16.458 23.47,15.755 23.113,15.399 22.708,15.399 v1(22.53,15.221)
MDI_R_N: P1.R8 R8.2 R12.2 U1.4 | length 22.4
  Top Layer w0.152: P1.R8@16.88,10.555 16.64,10.795 15.732,10.795 15.351,10.414 15.351,9.16 15.786,8.725 18.885,8.725 v1(19.177,9.017) R8.2@19.693,9.017
  Bottom Layer w0.152: U1.4@19.116,14.802 19.116,13.807 18.923,13.614 18.39,13.614 18.072,13.297 17.983,13.207 17.983,9.22 17.526,8.763 15.748,8.763 15.351,9.16 15.351,10.414 ; v1(19.177,9.017) R12.2@19.693,9.017 ; 15.351,10.414 15.732,10.795 ; 15.351,10.414 15.732,10.795 ; 15.732,10.795 P1.R8@16.64,10.795 ; 15.732,10.795 P1.R8@16.64,10.795 ; P1.R8@16.64,10.795 P1.R8@16.88,10.555 P1.R8@16.64,10.795
MDI_R_P: P1.R7 R7.2 R11.2 U1.3 | length 22.4
  Top Layer w0.152: P1.R7@14.34,11.825 15.046,11.119 15.046,9.034 15.66,8.42 18.885,8.42 v1(19.177,8.128) R7.2@19.693,8.128
  Bottom Layer w0.152: U1.3@19.116,12.122 19.116,13.117 18.923,13.31 18.517,13.31 18.288,13.081 18.288,9.094 17.652,8.458 15.622,8.458 15.532,8.547 15.046,9.034 15.046,11.119 ; v1(19.177,8.128) R11.2@19.693,8.128 ; 15.046,11.119 P1.R7@14.34,11.825 15.046,11.119
MDI_T_N: P1.R2 R5.2 R10.2 U1.6 | length 19.3
  Top Layer w0.152: P1.R2@16.88,18.175 16.24,18.815 16.24,19.161 16.548,19.469 18.885,19.469 v1(19.177,19.177) R5.2@19.693,19.177
  Bottom Layer w0.152: P1.R2@16.88,18.175 16.24,18.815 16.24,19.304 16.621,19.685 17.653,19.685 18.034,19.304 18.034,16.968 18.619,16.383 21.082,16.383 21.717,15.748 21.717,13.843 21.488,13.614 21.209,13.614 21.016,13.807 U1.6@21.016,14.802 ; v1(19.177,19.177) R10.2@19.693,19.177
MDI_T_P: P1.R1 R4.2 R9.2 U1.1 | length 21.5
  Top Layer w0.152: P1.R1@14.34,19.445 16.093,19.445 16.422,19.774 18.885,19.774 v1(19.177,20.066) R4.2@19.693,20.066
  Bottom Layer w0.152: P1.R1@14.34,19.445 15.95,19.445 16.495,19.99 17.779,19.99 18.339,19.43 18.339,17.094 18.745,16.688 21.208,16.688 22.022,15.874 22.022,13.717 21.933,13.627 21.615,13.31 21.209,13.31 21.016,13.117 U1.1@21.016,12.122 ; v1(19.177,20.066) R9.2@19.693,20.066
NetC4_2: C4.2 R9.1 R10.1 | length 1.8
  Bottom Layer w0.381: C4.2@20.693,18.288 R10.1@20.693,19.177 R9.1@20.693,20.066
NetC5_2: C5.2 R11.1 R12.1 | length 1.8
  Bottom Layer w0.381: R11.1@20.693,8.128 R12.1@20.693,9.017 C5.2@20.693,9.906
NetC6_2: C6.2 P1.R3 | length 5.4
  Top Layer w0.381: P1.R3@14.34,16.905 14.354,16.891 C6.2@19.693,16.891
NetC11_2: C11.2 U5.2 | length 1.8
  Top Layer w0.152: C11.2@36.957,12.692 v1(36.957,13.208)
  Bottom Layer w0.152: U5.2@36.931,11.912 36.931,13.182 v1(36.957,13.208)
NetC12_2: C12.2 U5.6 | length 2.4
  Top Layer w0.152: C12.2@35.052,12.692 v1(35.052,13.208)
  Bottom Layer w0.152: U5.6@34.331,11.912 34.331,12.995 34.544,13.208 v1(35.052,13.208)
NetC13_1: C13.1 U5.1 | length 1.6
  Bottom Layer w0.152: U5.1@37.581,11.912 37.581,10.544 C13.1@37.711,10.414
NetC13_2: C13.2 U5.3 | length 1.7
  Bottom Layer w0.152: U5.3@36.281,11.912 36.281,10.844 C13.2@36.711,10.414
NetC14_1: C14.1 U5.4 | length 1.5
  Bottom Layer w0.152: U5.4@35.631,11.912 35.631,10.462 C14.1@35.679,10.414
NetC14_2: C14.2 U5.5 | length 1.6
  Bottom Layer w0.152: C14.2@34.679,10.414 34.981,10.716 U5.5@34.981,11.912
NetD1_2: D1.2 R36.1 | length 1.5
  Top Layer w0.152: v1(33.528,26.505) D1.2@34.29,26.505
  Bottom Layer w0.152: v1(33.528,26.505) 33.828,26.805 R36.1@34.163,26.805
NetD2_2: D2.2 R37.1 | length 7.7
  Top Layer w0.152: R37.1@28.829,25.519 29.37,26.06 30.328,26.06 30.632,25.756 35.357,25.756 35.56,25.959 D2.2@35.56,26.505
NetD3_2: D3.2 R38.1 | length 7.7
  Bottom Layer w0.152: R38.1@28.829,25.519 29.37,26.06 30.328,26.06 30.632,25.756 35.357,25.756 35.56,25.959 D3.2@35.56,26.505
NetD4_2: D4.2 R39.1 | length 8
  Top Layer w0.152: R39.1@29.718,25.519 29.786,25.451 36.576,25.451 36.83,25.705 D4.2@36.83,26.505
NetD5_2: D5.2 R40.1 | length 8
  Bottom Layer w0.152: R40.1@29.718,25.519 29.786,25.451 36.576,25.451 36.83,25.705 D5.2@36.83,26.505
